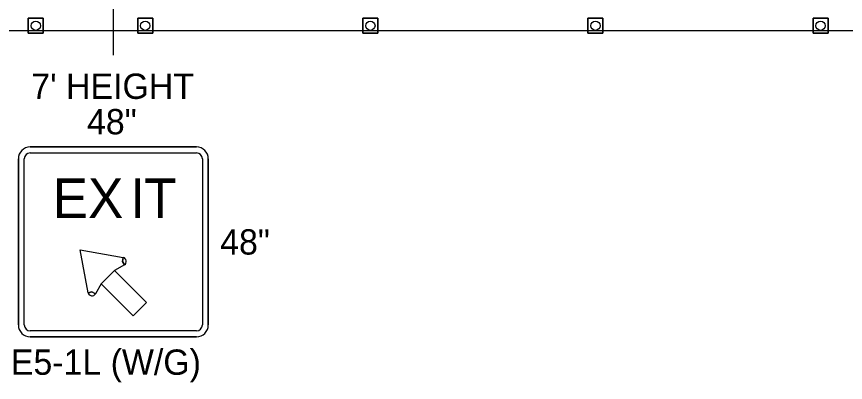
# Model space of a CAD drawing. Extents: x 99999 to 100116, y 99995 to 100013.
# Drawn here: x 100062.573 to 100064.93, y 100005.559 to 100006.599 of the extents above; entities that cross this region are included whole.
import ezdxf

# ---------------------------------------------------------------- set-up
doc = ezdxf.new("R2010")
doc.units = 0
for name, color, linetype in [('TR_SN_ConstructionSigns', 7, 'Continuous'), ('TR_WZ_TrafficCone', 7, 'Continuous'), ('TR_WZ_WorkZoneDetails', 7, 'Continuous')]:
    doc.layers.add(name, color=color, linetype=linetype)

msp = doc.modelspace()

# ---------------------------------------------------------------- linework, layer by layer
at = {"layer": 'TR_SN_ConstructionSigns'}
for p, q in [((100062.6119, 100006.2284), (100063.0844, 100006.2284)), ((100063.0844, 100006.2284), (100062.6119, 100006.2284)), ((100063.0844, 100006.2284), (100062.6119, 100006.2284)), ((100063.0844, 100006.2284), (100062.6119, 100006.2284)), ((100063.0844, 100006.2284), (100062.6119, 100006.2284)), ((100063.0844, 100006.2284), (100063.0844, 100006.2284)), ((100062.5782, 100005.7221), (100062.5782, 100006.1946)), ((100062.5782, 100006.1946), (100062.5782, 100006.1946)), ((100062.5782, 100006.1946), (100062.5782, 100005.7221)), ((100062.5782, 100006.1946), (100062.5782, 100005.7221)), ((100062.5782, 100006.1946), (100062.5782, 100005.7221)), ((100062.5782, 100006.1946), (100062.5782, 100005.7221)), ((100062.595, 100005.7221), (100062.595, 100006.1946)), ((100062.6119, 100006.2115), (100063.0844, 100006.2115)), ((100063.1013, 100006.1946), (100063.1013, 100005.7221)), ((100063.1182, 100006.1946), (100063.1182, 100005.7221)), ((100063.1182, 100005.7221), (100063.1182, 100006.1946)), ((100063.1182, 100005.7221), (100063.1182, 100006.1946)), ((100063.1182, 100005.7221), (100063.1182, 100006.1946)), ((100063.1182, 100005.7221), (100063.1182, 100006.1946)), ((100062.7542, 100005.9363), (100062.8765, 100005.914)), ((100062.7765, 100005.814), (100062.7542, 100005.9363)), ((100062.8765, 100005.914), (100062.874, 100005.903)), ((100062.874, 100005.903), (100062.8765, 100005.914)), ((100062.8798, 100005.8934), (100062.8516, 100005.8767)), ((100062.874, 100005.903), (100062.8798, 100005.8934)), ((100062.8798, 100005.8934), (100062.874, 100005.903)), ((100062.8139, 100005.8389), (100062.8516, 100005.8767)), ((100062.8516, 100005.8767), (100062.8139, 100005.8389)), ((100062.8516, 100005.8767), (100062.9421, 100005.7862)), ((100062.8139, 100005.8389), (100062.7972, 100005.8108)), ((100062.9043, 100005.7484), (100062.8139, 100005.8389)), ((100062.7875, 100005.8165), (100062.7765, 100005.814)), ((100062.7765, 100005.814), (100062.7875, 100005.8165)), ((100062.7972, 100005.8108), (100062.7875, 100005.8165)), ((100062.7875, 100005.8165), (100062.7972, 100005.8108)), ((100062.9421, 100005.7862), (100062.9043, 100005.7484)), ((100063.1182, 100005.7221), (100063.1182, 100005.7221)), ((100063.0844, 100005.7053), (100062.6119, 100005.7053)), ((100063.0844, 100005.6884), (100062.6119, 100005.6884)), ((100062.6119, 100005.6884), (100062.6119, 100005.6884)), ((100062.6119, 100005.6884), (100063.0844, 100005.6884)), ((100062.6119, 100005.6884), (100063.0844, 100005.6884)), ((100062.6119, 100005.6884), (100063.0844, 100005.6884))]:
    msp.add_line(p, q, dxfattribs=at)
for points in [[(100062.6119, 100005.6884), (100062.6119, 100005.6884)], [(100062.6119, 100005.6884), (100063.0844, 100005.6884), (100063.0844, 100005.6884)]]:
    msp.add_lwpolyline(points, dxfattribs=at)
for centre, radius, start, end in [((100062.6119, 100006.1946), 0.0338, 90, 180), ((100062.6119, 100006.1946), 0.0338, 90, 180), ((100062.6119, 100006.1946), 0.0338, 90, 180), ((100062.6119, 100006.1946), 0.0338, 90, 180), ((100062.6119, 100006.1946), 0.0338, 90, 180), ((100063.0844, 100006.1946), 0.0338, 360, 90), ((100063.0844, 100006.1946), 0.0338, 360, 90), ((100063.0844, 100006.1946), 0.0338, 360, 90), ((100063.0844, 100006.1946), 0.0338, 360, 90), ((100063.0844, 100006.1946), 0.0338, 360, 90), ((100062.6119, 100006.1946), 0.0169, 90, 180), ((100063.0844, 100006.1946), 0.0169, 360, 90), ((100062.874, 100005.903), 0.0112, 300.6741, 77.2288), ((100062.7875, 100005.8165), 0.0112, 192.7712, 329.3259), ((100062.6119, 100005.7221), 0.0338, 180, 270), ((100062.6119, 100005.7221), 0.0338, 180, 270), ((100062.6119, 100005.7221), 0.0338, 180, 270), ((100062.6119, 100005.7221), 0.0338, 180, 270), ((100062.6119, 100005.7221), 0.0338, 180, 270), ((100062.6119, 100005.7221), 0.0169, 180, 270), ((100063.0844, 100005.7221), 0.0338, 270, 0), ((100063.0844, 100005.7221), 0.0338, 270, 0), ((100063.0844, 100005.7221), 0.0338, 270, 0), ((100063.0844, 100005.7221), 0.0338, 270, 0), ((100063.0844, 100005.7221), 0.0169, 270, 0), ((100063.0844, 100005.7221), 0.0338, 270, 0)]:
    msp.add_arc(centre, radius, start, end, dxfattribs=at)
at = {"layer": 'TR_WZ_TrafficCone'}
for points in [[(100062.6062, 100006.552), (100062.6489, 100006.552), (100062.6489, 100006.5947), (100062.6062, 100006.5947), (100062.6062, 100006.552)], [(100062.6062, 100006.5947), (100062.6489, 100006.5947), (100062.6489, 100006.552), (100062.6062, 100006.552), (100062.6062, 100006.5947)], [(100062.9176, 100006.552), (100062.9603, 100006.552), (100062.9603, 100006.5947), (100062.9176, 100006.5947), (100062.9176, 100006.552)], [(100062.9176, 100006.5947), (100062.9603, 100006.5947), (100062.9603, 100006.552), (100062.9176, 100006.552), (100062.9176, 100006.5947)], [(100063.5576, 100006.552), (100063.6003, 100006.552), (100063.6003, 100006.5947), (100063.5576, 100006.5947), (100063.5576, 100006.552)], [(100063.5576, 100006.5947), (100063.6003, 100006.5947), (100063.6003, 100006.552), (100063.5576, 100006.552), (100063.5576, 100006.5947)], [(100064.1976, 100006.552), (100064.2403, 100006.552), (100064.2403, 100006.5947), (100064.1976, 100006.5947), (100064.1976, 100006.552)], [(100064.1976, 100006.5947), (100064.2403, 100006.5947), (100064.2403, 100006.552), (100064.1976, 100006.552), (100064.1976, 100006.5947)], [(100064.8376, 100006.552), (100064.8803, 100006.552), (100064.8803, 100006.5947), (100064.8376, 100006.5947), (100064.8376, 100006.552)], [(100064.8376, 100006.5947), (100064.8803, 100006.5947), (100064.8803, 100006.552), (100064.8376, 100006.552), (100064.8376, 100006.5947)]]:
    msp.add_lwpolyline(points, dxfattribs=at)
for centre in [(100062.6276, 100006.5734), (100062.9389, 100006.5734), (100063.5789, 100006.5734), (100064.2189, 100006.5734), (100064.8589, 100006.5734)]:
    msp.add_circle(centre, 0.0133, dxfattribs=at)
at = {"layer": 'TR_WZ_WorkZoneDetails'}
for p, q in [((100062.8482, 100006.4892), (100062.8482, 100006.6831)), ((100060.32, 100006.56), (100067.555, 100006.56))]:
    msp.add_line(p, q, dxfattribs=at)

# ---------------------------------------------------------------- texts
at = {"layer": 'TR_SN_ConstructionSigns'}
for s, height, p in [("7' HEIGHT", 0.072, (100062.615, 100006.3652)), ('48"', 0.072, (100062.7734, 100006.2644)), ('E', 0.1125, (100062.676, 100006.0263)), ('X', 0.1125, (100062.7762, 100006.0263)), ('I', 0.1125, (100062.8965, 100006.0263)), ('T', 0.1125, (100062.9359, 100006.0263)), ('48"', 0.072, (100063.152, 100005.9224)), ('E5-1L (W/G)', 0.072, (100062.5569, 100005.5804))]:
    msp.add_text(s, height=height, rotation=360, dxfattribs=at).set_placement(p)

doc.saveas('drawing.dxf')
